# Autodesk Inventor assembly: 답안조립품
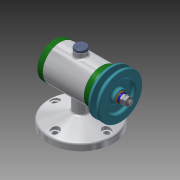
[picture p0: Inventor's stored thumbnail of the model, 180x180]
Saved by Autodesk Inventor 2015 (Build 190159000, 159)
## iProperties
Created: 2018-12
Part Number: 답안조립품
Document SubType Name: Assembly
Designer: now
Author: now
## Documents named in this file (15)
- C:\Users\now\Desktop\481207V1055\답안조립품.iam
- C:\Users\now\Desktop\481207V1055\V벨트풀리.ipt
- C:\Users\now\Desktop\481207V1055\고무캡.ipt
- C:\Users\now\Desktop\481207V1055\너트 M8.ipt
- 너트 M8.ipt
- C:\Users\now\Desktop\481207V1055\뒤커버.ipt
- C:\Users\now\Desktop\481207V1055\베어링 15 x 32 x 9.ipt
- C:\Users\now\Desktop\481207V1055\본체.ipt
- C:\Users\now\Desktop\481207V1055\볼트 M4 x 12.ipt
- C:\Users\now\Desktop\481207V1055\스프링와셔 8.ipt
- C:\Users\now\Desktop\481207V1055\앞커버.ipt
- C:\Users\now\Desktop\481207V1055\오일 실 15 25 7.ipt
- C:\Users\now\Desktop\481207V1055\와셔 8x17.ipt
- C:\Users\now\Desktop\481207V1055\축.ipt
- C:\Users\now\Desktop\481207V1055\키 3 x 3 x 12.ipt
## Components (2 placed, 2 different names)
1. V벨트풀리:1 — 각도:2
2. 고무캡:1
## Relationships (1: Angle 1)
- 각도:2 [Angle]: V벨트풀리:1
